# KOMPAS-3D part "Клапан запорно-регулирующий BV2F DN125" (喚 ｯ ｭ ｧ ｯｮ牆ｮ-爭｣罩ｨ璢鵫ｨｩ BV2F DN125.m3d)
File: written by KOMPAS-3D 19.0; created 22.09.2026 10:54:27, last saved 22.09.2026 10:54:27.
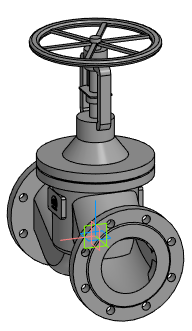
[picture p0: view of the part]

Document properties: Автор: Энергия; Полное имя файла: Z:\3.Личные\sachek\Dendor\_3D для проектировщиков\5.7 Клапан запорно-регулирующий BV2F\BV2F_STP\Клапан запорно-регулирующий BV2F DN125.m3d

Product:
- Part/product: Клапан запорно-регулирующий BV2F DN125

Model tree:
1. Операция без истории:1  (labels: Клапан запорно-регулирующий BV2F DN125)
